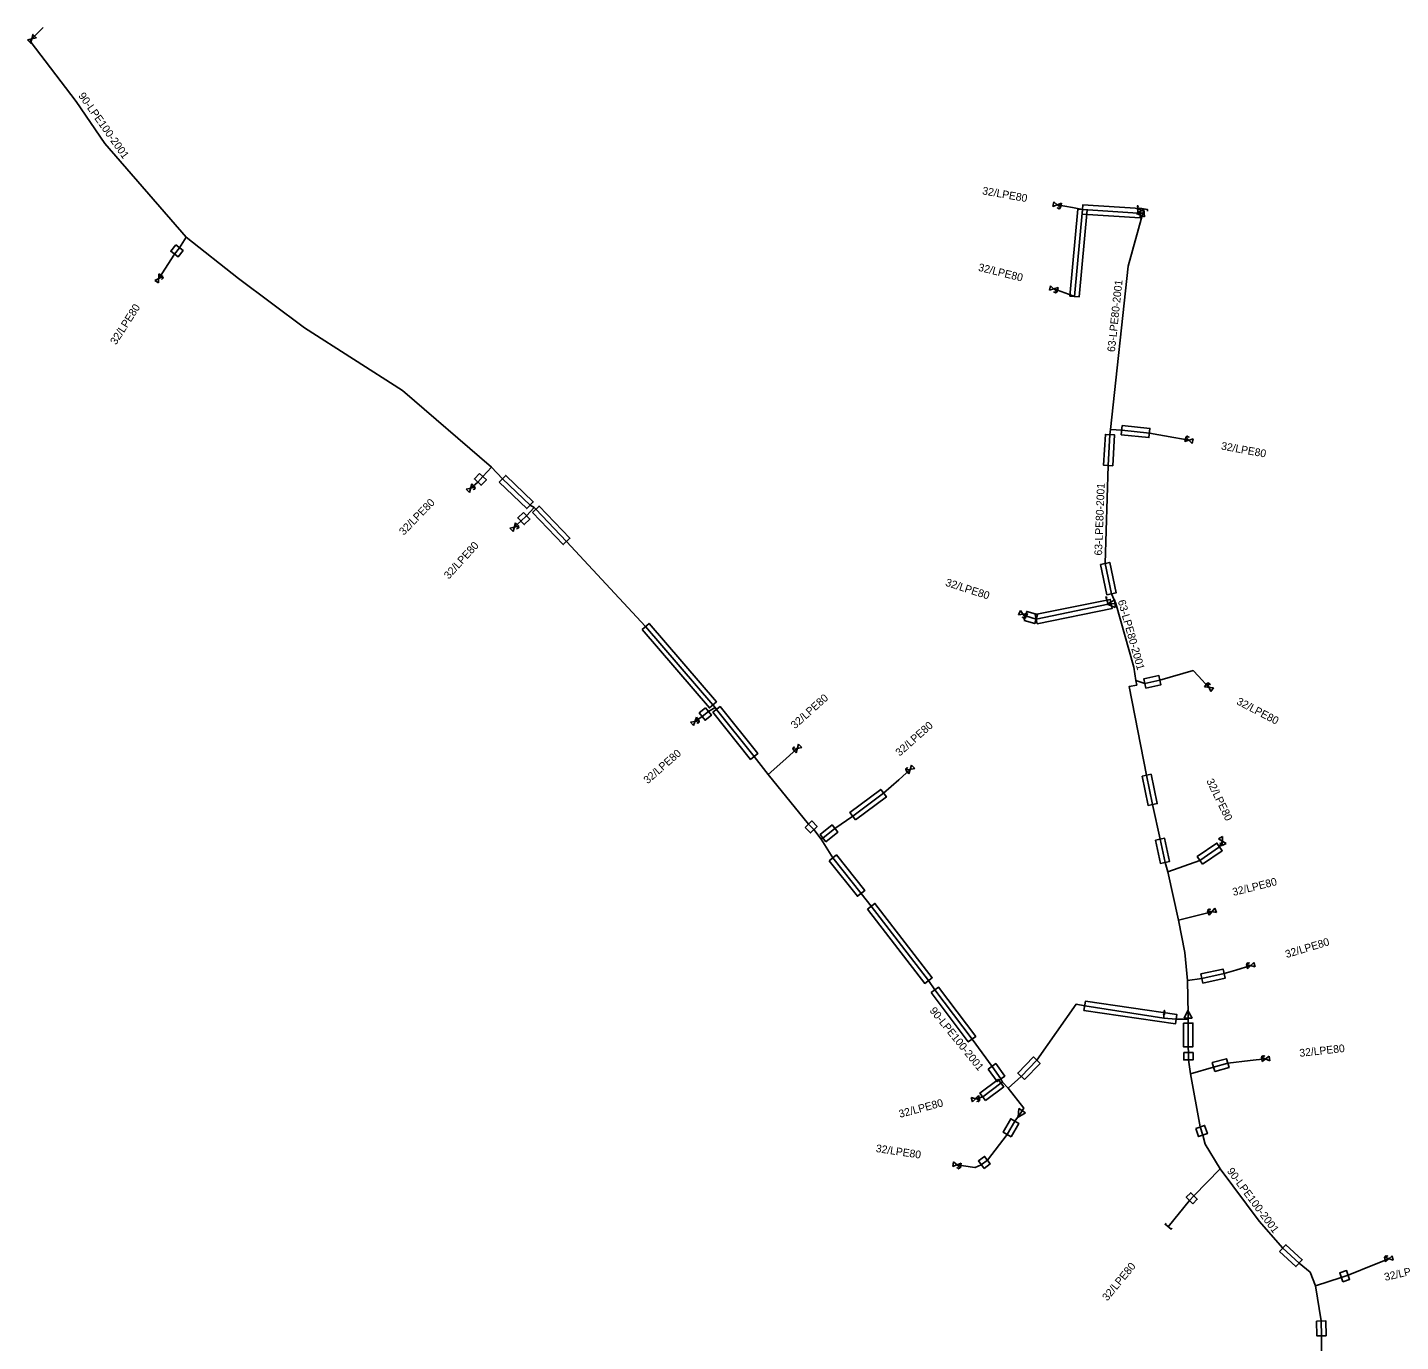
# Model space of a CAD drawing. Extents: x -787723 to -786204, y -1153846 to -1152384.
# Drawn here: x -786553.6 to -786376.3, y -1153467.7 to -1153297.9 of the extents above; entities that cross this region are included whole.
import ezdxf

# ---------------------------------------------------------------- set-up
doc = ezdxf.new("R2010")
doc.units = 0
for name, color, linetype in [('Vrstva 1', 7, 'Continuous'), ('Vrstva 21', 7, 'Continuous'), ('Vrstva 22', 7, 'Continuous'), ('Vrstva 26', 7, 'Continuous'), ('Vrstva 28', 7, 'Continuous'), ('Vrstva 29', 7, 'Continuous'), ('Vrstva 31', 7, 'Continuous'), ('Vrstva 32', 7, 'Continuous'), ('Vrstva 33', 7, 'Continuous')]:
    doc.layers.add(name, color=color, linetype=linetype)

# ---------------------------------------------------------------- blocks, each defined once
blk = doc.blocks.new('DEC122')
at = {"layer": 'Vrstva 1'}
for p, q in [((-0.5, 0.5), (0.5, 0)), ((-0.5, -0.5), (-0.5, 0.5)), ((0.5, 0), (-0.5, -0.5))]:
    blk.add_line(p, q, dxfattribs=at)
blk = doc.blocks.new('DEC063-SN')
at = {"layer": 'Vrstva 1'}
for p, q in [((-0.5, -0.3), (0.5, 0.3)), ((0.5, -0.3), (-0.5, 0.3)), ((-0.5, 0.3), (-0.5, -0.3)), ((0.5, 0.3), (0.5, -0.3)), ((0.126, -0.318), (0.126, -0.458)), ((0.126, -0.384), (0.206, -0.384)), ((0.206, -0.458), (0.206, -0.318)), ((0.366, -0.458), (0.366, -0.318))]:
    blk.add_line(p, q, dxfattribs=at)
for points in [[(0.246, -0.318), (0.246, -0.418), (0.252, -0.438), (0.264, -0.451), (0.281, -0.458), (0.292, -0.458), (0.309, -0.451), (0.321, -0.438), (0.326, -0.418), (0.326, -0.318)], [(0.366, -0.318), (0.418, -0.318), (0.435, -0.325), (0.441, -0.331), (0.446, -0.344), (0.446, -0.364), (0.441, -0.378), (0.435, -0.384), (0.418, -0.391), (0.366, -0.391)]]:
    blk.add_lwpolyline(points, dxfattribs=at)
blk = doc.blocks.new('DEC130-SN')
at = {"layer": 'Vrstva 1'}
blk.add_lwpolyline([(0.2, 0.5), (0, 0.5), (0, -0.5), (0.2, -0.5)], dxfattribs=at)
blk = doc.blocks.new('DEC130')
at = {"layer": 'Vrstva 1'}
blk.add_lwpolyline([(0.2, 0.5), (0, 0.5), (0, -0.5), (0.2, -0.5)], dxfattribs=at)
blk = doc.blocks.new('DEC124')
at = {"layer": 'Vrstva 1'}
blk.add_lwpolyline([(-0.5, 0.3), (0.5, -0.3), (0.5, 0.3), (-0.5, -0.3), (-0.5, 0.3)], dxfattribs=at)
blk = doc.blocks.new('DEC127')
at = {"layer": 'Vrstva 1'}
for p, q in [((0, 0.56), (0, 0.99)), ((0, 0.42), (0, -0.01))]:
    blk.add_line(p, q, dxfattribs=at)
blk.add_lwpolyline([(-0.07, 0.82), (0, 0.99), (0.07, 0.82)], dxfattribs=at)
blk.add_circle((0, 0.49), 0.07, dxfattribs=at)

msp = doc.modelspace()

# ---------------------------------------------------------------- linework, layer by layer
at = {"layer": 'Vrstva 21'}
for points in [[(-786553.08, -1153299.41), (-786553.28, -1153299.71), (-786547.37, -1153307.52), (-786543.64, -1153312.95), (-786533.13, -1153325.03), (-786526.37, -1153330.38), (-786517.86, -1153336.74), (-786505.2, -1153344.84), (-786493.71, -1153354.74), (-786492.27, -1153356.25), (-786488.71, -1153359.68), (-786488.19, -1153359.97), (-786487.97, -1153360.2), (-786484, -1153364.35), (-786473.8, -1153375.34), (-786465.09, -1153385.46), (-786464.81, -1153385.79), (-786464.63, -1153386.05), (-786459.76, -1153392.14), (-786457.96, -1153394.48), (-786452.75, -1153400.89), (-786452.06, -1153401.59), (-786451.12, -1153402.83), (-786449.61, -1153405.23), (-786445.94, -1153409.83), (-786444.63, -1153411.49), (-786437.24, -1153421.09), (-786436.43, -1153422.28), (-786431.61, -1153428.66), (-786429.03, -1153432.17), (-786427.88, -1153433.78), (-786427.68, -1153434.23), (-786426.96, -1153434.97)], [(-786551.62, -1153297.94), (-786553.08, -1153299.41)], [(-786413.03, -1153372.38), (-786413.59, -1153371.11), (-786414.42, -1153367.19), (-786414.01, -1153354.54), (-786413.79, -1153350.55), (-786413.74, -1153349.89), (-786411.46, -1153328.77), (-786409.56, -1153321.92)], [(-786409.56, -1153321.92), (-786409.87, -1153321.94)], [(-786409.56, -1153321.92), (-786409.42, -1153321.39)], [(-786413.03, -1153372.38), (-786413.64, -1153372.43)], [(-786403.7, -1153425.44), (-786403.79, -1153421.08), (-786404.12, -1153417.46), (-786404.94, -1153413.27), (-786406.33, -1153407.02), (-786406.68, -1153405.83), (-786407.32, -1153402.83), (-786408.28, -1153398.33), (-786409.06, -1153394.55), (-786411.29, -1153383.09), (-786410.34, -1153382.91), (-786410.44, -1153382.32), (-786410.71, -1153380.59), (-786413.03, -1153372.38)], [(-786426.96, -1153434.97), (-786425.28, -1153433.47), (-786423.24, -1153431.37), (-786418.17, -1153424.14), (-786417.06, -1153424.35), (-786406.85, -1153425.93), (-786405.23, -1153426.07), (-786403.68, -1153426.09)], [(-786403.68, -1153426.09), (-786403.7, -1153425.44)], [(-786403.68, -1153426.09), (-786403.67, -1153426.59), (-786403.69, -1153429.66), (-786403.66, -1153430.4), (-786403.66, -1153431.35), (-786403.4, -1153433.13), (-786402.13, -1153440), (-786401.78, -1153441.05), (-786401.48, -1153442.23), (-786399.56, -1153445.43), (-786394.52, -1153452.17), (-786391.47, -1153455.66), (-786389.35, -1153457.6), (-786387.92, -1153458.78), (-786387.24, -1153460.52), (-786386.49, -1153465.07), (-786386.46, -1153466.99), (-786386.46, -1153470.29), (-786386.3, -1153473.43), (-786384.91, -1153475.81), (-786384.52, -1153476.69), (-786384.18, -1153477.22), (-786383.69, -1153478.09), (-786382, -1153481.15)], [(-786426.96, -1153434.97), (-786424.92, -1153437.57), (-786425.4, -1153438.32)]]:
    msp.add_lwpolyline(points, dxfattribs=at)
at = {"layer": 'Vrstva 29'}
for points in [[(-786417.94, -1153321.42), (-786416.74, -1153321.52), (-786417.76, -1153332.74), (-786418.96, -1153332.64)], [(-786417.38, -1153322.07), (-786417.3, -1153320.87), (-786409.83, -1153321.34), (-786409.91, -1153322.54)], [(-786534.48, -1153326.03), (-786533.54, -1153326.77), (-786534.19, -1153327.59), (-786535.13, -1153326.85)], [(-786413.41, -1153354.57), (-786414.61, -1153354.51), (-786414.39, -1153350.52), (-786413.19, -1153350.58)], [(-786412.33, -1153350.59), (-786412.21, -1153349.39), (-786408.63, -1153349.74), (-786408.75, -1153350.94)], [(-786495.24, -1153355.57), (-786494.36, -1153356.39), (-786495.03, -1153357.1), (-786495.91, -1153356.28)], [(-786492.69, -1153356.68), (-786491.85, -1153355.82), (-786488.29, -1153359.25), (-786489.13, -1153360.11)], [(-786488.4, -1153360.61), (-786487.54, -1153359.78), (-786483.57, -1153363.94), (-786484.43, -1153364.76)], [(-786489.58, -1153360.6), (-786488.74, -1153361.46), (-786489.47, -1153362.17), (-786490.31, -1153361.31)], [(-786415.01, -1153367.31), (-786413.83, -1153367.06), (-786413, -1153370.99), (-786414.18, -1153371.23)], [(-786423.21, -1153374.98), (-786423.45, -1153373.8), (-786413.76, -1153371.84), (-786413.52, -1153373.02)], [(-786424.89, -1153374.55), (-786424.55, -1153373.4), (-786423.16, -1153373.81), (-786423.5, -1153374.97)], [(-786474.25, -1153375.73), (-786473.34, -1153374.95), (-786464.64, -1153385.07), (-786465.54, -1153385.85)], [(-786409.17, -1153383.29), (-786409.43, -1153382.11), (-786407.46, -1153381.68), (-786407.2, -1153382.86)], [(-786466.03, -1153385.86), (-786465.29, -1153386.8), (-786466.11, -1153387.45), (-786466.85, -1153386.51)], [(-786465.1, -1153386.42), (-786464.16, -1153385.68), (-786459.29, -1153391.77), (-786460.23, -1153392.51)], [(-786409.65, -1153394.67), (-786408.47, -1153394.43), (-786407.69, -1153398.21), (-786408.87, -1153398.45)], [(-786446.67, -1153400.32), (-786447.39, -1153399.36), (-786443.4, -1153396.39), (-786442.68, -1153397.35)], [(-786453.18, -1153401.31), (-786452.32, -1153400.47), (-786451.63, -1153401.17), (-786452.49, -1153402.01)], [(-786450.51, -1153403.16), (-786451.25, -1153402.22), (-786449.69, -1153400.98), (-786448.95, -1153401.92)], [(-786407.91, -1153402.96), (-786406.73, -1153402.7), (-786406.09, -1153405.7), (-786407.27, -1153405.96)], [(-786401.83, -1153406.05), (-786402.51, -1153405.06), (-786399.97, -1153403.32), (-786399.29, -1153404.31)], [(-786450.08, -1153405.6), (-786449.14, -1153404.85), (-786445.47, -1153409.46), (-786446.41, -1153410.2)], [(-786445.1, -1153411.85), (-786444.15, -1153411.12), (-786436.76, -1153420.72), (-786437.71, -1153421.46)], [(-786401.78, -1153421.41), (-786402.04, -1153420.23), (-786399.17, -1153419.6), (-786398.91, -1153420.78)], [(-786436.91, -1153422.64), (-786435.95, -1153421.92), (-786431.13, -1153428.3), (-786432.09, -1153429.02)], [(-786417.15, -1153424.94), (-786416.97, -1153423.76), (-786405.14, -1153425.48), (-786405.32, -1153426.66)], [(-786404.27, -1153426.59), (-786403.07, -1153426.59), (-786403.09, -1153429.66), (-786404.29, -1153429.66)], [(-786404.26, -1153430.4), (-786403.06, -1153430.4), (-786403.06, -1153431.35), (-786404.26, -1153431.35)], [(-786429.52, -1153432.52), (-786428.54, -1153431.82), (-786427.39, -1153433.43), (-786428.37, -1153434.13)], [(-786424.85, -1153433.89), (-786425.71, -1153433.05), (-786423.67, -1153430.95), (-786422.81, -1153431.79)], [(-786400.25, -1153432.84), (-786400.57, -1153431.68), (-786398.73, -1153431.18), (-786398.41, -1153432.34)], [(-786429.87, -1153436.58), (-786430.59, -1153435.62), (-786428.23, -1153433.85), (-786427.51, -1153434.81)], [(-786426.57, -1153441.26), (-786427.61, -1153440.66), (-786426.61, -1153438.95), (-786425.57, -1153439.55)], [(-786402.7, -1153440.19), (-786401.56, -1153439.81), (-786401.21, -1153440.86), (-786402.35, -1153441.24)], [(-786430.06, -1153445.36), (-786430.78, -1153444.4), (-786429.99, -1153443.81), (-786429.27, -1153444.77)], [(-786403.09, -1153449.92), (-786403.94, -1153449.07), (-786403.36, -1153448.5), (-786402.52, -1153449.34)], [(-786391.88, -1153456.1), (-786391.06, -1153455.22), (-786388.94, -1153457.16), (-786389.76, -1153458.04)], [(-786383.71, -1153460.01), (-786384.11, -1153458.87), (-786383.23, -1153458.56), (-786382.83, -1153459.7)], [(-786387.09, -1153465.08), (-786385.89, -1153465.06), (-786385.86, -1153466.98), (-786387.06, -1153467)]]:
    msp.add_lwpolyline(points, close=True, dxfattribs=at)
at = {"layer": 'Vrstva 31'}
for points in [[(-786417.34, -1153321.47), (-786418.36, -1153332.69), (-786419.15, -1153332.41), (-786421.04, -1153331.72)], [(-786417.3, -1153321.47), (-786417.34, -1153321.47), (-786418.63, -1153321.22), (-786420.61, -1153320.87)], [(-786409.87, -1153321.94), (-786410.2, -1153321.94), (-786417.3, -1153321.47)], [(-786533.13, -1153325.03), (-786534.01, -1153326.4), (-786534.66, -1153327.22), (-786536.68, -1153330.37)], [(-786413.74, -1153349.89), (-786412.27, -1153349.99), (-786408.69, -1153350.34), (-786405.55, -1153350.91), (-786403.58, -1153351.27)], [(-786493.71, -1153354.74), (-786494.8, -1153355.98), (-786495.47, -1153356.69), (-786496.38, -1153357.46)], [(-786488.19, -1153359.97), (-786489.16, -1153361.03), (-786489.89, -1153361.74), (-786490.75, -1153362.51)], [(-786413.64, -1153372.43), (-786414.03, -1153372.45), (-786423.33, -1153374.39), (-786424.72, -1153373.98), (-786425.03, -1153373.75)], [(-786410.44, -1153382.32), (-786409.3, -1153382.7), (-786407.33, -1153382.27), (-786403.06, -1153381.03), (-786402.37, -1153381.75), (-786401.01, -1153383.2)], [(-786464.81, -1153385.79), (-786465.66, -1153386.33), (-786466.48, -1153386.98), (-786467.42, -1153387.6)], [(-786457.96, -1153394.48), (-786455.68, -1153392.45), (-786454.19, -1153391.12)], [(-786451.12, -1153402.83), (-786450.88, -1153402.69), (-786449.32, -1153401.45), (-786447.03, -1153399.84), (-786443.04, -1153396.87), (-786441.09, -1153395.13), (-786439.59, -1153393.8)], [(-786406.33, -1153407.02), (-786402.17, -1153405.56), (-786399.63, -1153403.82), (-786399.27, -1153403.07)], [(-786404.94, -1153413.27), (-786400.61, -1153412.19)], [(-786403.79, -1153421.08), (-786401.91, -1153420.82), (-786399.04, -1153420.19), (-786397.52, -1153419.74), (-786395.6, -1153419.16)], [(-786403.4, -1153433.13), (-786400.41, -1153432.26), (-786398.57, -1153431.76), (-786395.67, -1153431.43), (-786393.68, -1153431.21)], [(-786427.68, -1153434.23), (-786427.87, -1153434.33), (-786430.23, -1153436.1), (-786431.16, -1153436.35)], [(-786425.4, -1153438.32), (-786426.09, -1153439.25), (-786427.09, -1153440.96), (-786429.63, -1153444.29), (-786430.42, -1153444.88), (-786431.21, -1153445.26), (-786431.56, -1153445.2), (-786433.57, -1153444.9)], [(-786399.56, -1153445.43), (-786402.94, -1153448.92), (-786403.52, -1153449.5), (-786406.28, -1153452.89)], [(-786387.24, -1153460.52), (-786383.91, -1153459.44), (-786383.03, -1153459.13), (-786379.62, -1153457.77), (-786377.76, -1153457.03)]]:
    msp.add_lwpolyline(points, dxfattribs=at)

# ---------------------------------------------------------------- block references
at = {"layer": 'Vrstva 22'}
for name, p, rotation in [('DEC124', (-786553.08, -1153299.41), 45.195547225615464), ('DEC130', (-786409.42, -1153321.39), -99.72262500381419)]:
    msp.add_blockref(name, p, dxfattribs=dict(at, rotation=rotation))
at = {"layer": 'Vrstva 26'}
for p, rotation in [((-786409.87, -1153321.94), -176.30861382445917), ((-786413.64, -1153372.43), -175.3141000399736), ((-786403.7, -1153425.44), 91.76239164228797), ((-786425.4, -1153438.32), -122.61924161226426)]:
    msp.add_blockref('DEC122', p, dxfattribs=dict(at, rotation=rotation))
at = {"layer": 'Vrstva 28'}
msp.add_blockref('DEC127', (-786410.2, -1153321.94), dxfattribs=at)
for p, rotation in [((-786414.03, -1153372.45), 15.269049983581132), ((-786406.85, -1153425.93), -5.229597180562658)]:
    msp.add_blockref('DEC127', p, dxfattribs=dict(at, rotation=rotation))
at = {"layer": 'Vrstva 32'}
for p, rotation in [((-786420.61, -1153320.87), -10.02448611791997), ((-786536.68, -1153330.37), 57.329172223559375), ((-786421.04, -1153331.72), -13.11199443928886), ((-786403.58, -1153351.27), 166.22145274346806), ((-786496.38, -1153357.46), 44.514769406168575), ((-786490.75, -1153362.51), 44.82453055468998), ((-786425.03, -1153373.75), -23.83776113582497), ((-786401.01, -1153383.2), 144.20445822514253), ((-786467.42, -1153387.6), 39.613308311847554), ((-786454.19, -1153391.12), -136.10529712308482), ((-786439.59, -1153393.8), -138.3105388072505), ((-786399.27, -1153403.07), -61.778588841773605), ((-786400.61, -1153412.19), -160.55323054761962), ((-786395.6, -1153419.16), -165.09330837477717), ((-786393.68, -1153431.21), -173.8273806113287), ((-786431.16, -1153436.35), 15.046391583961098), ((-786433.57, -1153444.9), -8.488944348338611), ((-786377.76, -1153457.03), -168.06001110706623)]:
    msp.add_blockref('DEC063-SN', p, dxfattribs=dict(at, rotation=rotation))
at = {"layer": 'Vrstva 33', "rotation": 49.956312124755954}
msp.add_blockref('DEC130-SN', (-786406.28, -1153452.89), dxfattribs=at)

# ---------------------------------------------------------------- texts
at = {"layer": 'Vrstva 21'}
for s, rotation, p in [('90-LPE100-2001', 305.398, (-786547.12, -1153306.77)), ('63-LPE80-2001', 83.839, (-786413.16, -1153339.91)), ('63-LPE80-2001', 87.789, (-786414.82, -1153366.18)), ('63-LPE80-2001', 285.779, (-786412.79, -1153372.04)), ('90-LPE100-2001', 309.104, (-786437.15, -1153425)), ('90-LPE100-2001', 306.788, (-786398.73, -1153445.72))]:
    msp.add_text(s, height=1, rotation=rotation, dxfattribs=at).set_placement(p)
at = {"layer": 'Vrstva 31'}
for rotation, p in [(349.976, (-786430.35, -1153319.49)), (346.086, (-786430.88, -1153329.36)), (57.329, (-786542.2, -1153339.02)), (349.644, (-786399.49, -1153352.46)), (45.779, (-786505.03, -1153363.62)), (47.807, (-786499.21, -1153369.29)), (342.019, (-786435.13, -1153370.05)), (41.753, (-786454.48, -1153388.62)), (332.466, (-786397.53, -1153385.33)), (41.562, (-786440.96, -1153392.16)), (41.114, (-786473.52, -1153395.73)), (295.921, (-786401.37, -1153395.28)), (14.005, (-786397.84, -1153410.16)), (16.809, (-786390.98, -1153418.19)), (6.309, (-786389.26, -1153430.95)), (15.046, (-786440.93, -1153438.83)), (351.511, (-786444.09, -1153443.23)), (50.488, (-786414.13, -1153462.56)), (13.035, (-786378.23, -1153459.9))]:
    msp.add_text('32/LPE80', height=1, rotation=rotation, dxfattribs=at).set_placement(p)

doc.saveas('drawing.dxf')
